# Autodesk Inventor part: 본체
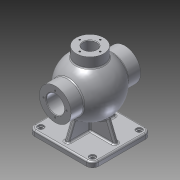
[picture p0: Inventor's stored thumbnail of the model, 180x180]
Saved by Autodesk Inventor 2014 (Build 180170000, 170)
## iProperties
Created: 2015-10
Part Number: 본체
Material: Aluminum 6061
Document SubType Name: Modeling
Designer: youjin20
Density: 2.71 g/cm^3
Appearance: Aluminum - Flat
Mass: 1509.58 g
Surface Area: 1153.86 cm^2
Volume: 557.04 cm^3
Author: youjin20
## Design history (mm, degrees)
sketch "Sketch2"
  geometry: L1 (50.5, -57.5)-(-50.5, -57.5); L2 (-62.5, -45.5)-(-62.5, 45.5); L3 (-50.5, 57.5)-(50.5, 57.5); L4 (62.5, 45.5)-(62.5, -45.5); L5 (62.5, -57.5)-(-62.5, 57.5); L6 (-62.5, -57.5)-(62.5, 57.5); A1 r 12 centre (50.5, 45.5) between (62.5, 45.5) and (50.5, 57.5); A2 r 12 centre (-50.5, 45.5) between (-50.5, 57.5) and (-62.5, 45.5); A3 r 12 centre (-50.5, -45.5) between (-62.5, -45.5) and (-50.5, -57.5); A4 r 12 centre (50.5, -45.5) between (50.5, -57.5) and (62.5, -45.5); 1 further point
  constraints: 12 end point, 8 point on circle, 8 point on line, 8 tangent, 4 centre point, 3 equal radius, 2 midpoint, 2 parallel, 1 horizontal, 1 perpendicular
  dimensions: "d0" = 125 distance of L5.end L6.end; "d1" = 115 distance of L6.start L5.end; "d2" = 12 radius of A1; "d3" = 101 distance of A2.centre A1.centre (derived)
extrude "Extrusion1" new body sketch "Sketch2" distance "d4" = 10; taper "d5" = 0 deg
sketch "Sketch3"
  geometry: A1 r 12 centre (50.5, -45.5) between (50.5, -57.5) and (62.5, -45.5) reference; A2 r 12 centre (50.5, 45.5) between (62.5, 45.5) and (50.5, 57.5) reference; A3 r 12 centre (-50.5, 45.5) between (-50.5, 57.5) and (-62.5, 45.5) reference; A4 r 12 centre (-50.5, -45.5) between (-62.5, -45.5) and (-50.5, -57.5) reference; 5 further points
  constraints: 4 coincident
hole "Hole1" sketch "Sketch3" at (-50.5, 45.5), (50.5, 45.5), (50.5, -45.5), (-50.5, -45.5) diameter "d6" = 8; stored, may be unused: countersink angle "d10" = 90 deg, drill point angle "d12" = 0 deg; dims "d7" = 6, "d8" = 12, "d9" = 3, "d11" = 8
sketch "Sketch4"
  geometry: L1 (-53, 85)-(-43, 85); L2 (-43, 85)-(43, 85); L3 (43, 85)-(53, 85); A1 r 53 centre (0, 85) between (-53, 85) and (53, 85); A2 r 43 centre (0, 85) between (-43, 85) and (43, 85); 2 further points
  constraints: 6 end point, 4 point on circle, 3 horizontal, 2 centre point, 2 coincident, 1 midpoint, 1 point on line, 1 vertical alignment
  dimensions: "d13" = 53 radius of A1; "d14" = 43 radius of A2; "d15" = 85 distance of point (0, 0) A2.centre
revolve "Revolution1" sketch "Sketch4" stored, may be unused: angle "d16" = 90 deg
workplane "Work Plane1"
sketch "Sketch5"
  geometry: C1 r 27 at (0, 0); 1 further point
  constraints: 1 centre point, 1 coincident
  dimensions: "d18" = 54 diameter of C1
extrude "Extrusion2" join sketch "Sketch5" stored distance "d19" = 10; taper "d20" = 0 deg
workplane "Work Plane2"
sketch "Sketch6"
  geometry: L1 (0, -27)-(0, 27) reference; L2 (0, 27)-(19.393, 27) reference; L3 (0, -27)-(19.393, -27) reference; 3 further points
  constraints: 1 horizontal alignment, 1 midpoint, 1 other
  dimensions: "d21" = 10 distance from line of point (10, 0) L1; "d120" = 27 distance from line of L3 point (10, 0) (derived)
emboss "Emboss1" sketch "Sketch6" dims "d0" = 125, "d1" = 115, "d2" = 12, "d3" = 101 (derived), "d23" = 0.5, "d24" = 0
sketch "Sketch7"
  geometry: L1 (4, 4)-(-4, 4); L2 (-4, 4)-(-4, -4); L3 (-4, -4)-(4, -4); L4 (4, -4)-(4, 4); L5 (4, 4)-(-4, -4); L6 (-4, 4)-(4, -4); 1 further point
  constraints: 12 end point, 2 midpoint, 2 parallel, 1 horizontal, 1 perpendicular
  dimensions: "d25" = 8 distance of L3.end L2.end; "d26" = 8 distance of L2.end L1.end
extrude "Extrusion3" join sketch "Sketch7" stored distance "d27" = 10; taper "d28" = 0 deg
sketch "Sketch8"
  geometry: L1 (-52.5, 10)-(-37.379, 47.426); L2 (52.5, 10)-(37.379, 47.426); L3 (62.5, 10)-(50.5, 10) reference; L4 (62.5, 0)-(62.5, 10) reference; L5 (-50.5, 10)-(-62.5, 10) reference; L6 (-62.5, 0)-(-62.5, 10) reference; A1 r 53 centre (0, 85) between (-27, 130.607) and (27, 130.607) reference; 1 further point
  constraints: 4 end point, 2 point on circle, 2 point on line
  dimensions: "d29" = 22 deg angle of L6 L1; "d30" = 22 deg angle of L2 L4; "d31" = 10 distance of L5.end L1.start; "d32" = 10 distance of L3.start L2.start
feature "Rib1" dims "d33" = 1, "d34" = 8, "d35" = 0, "d36" = 0, "d37" = 1, "d38" = 1
feature "Rib2" dims "d39" = 1, "d40" = 8, "d41" = 0, "d42" = 0, "d43" = 1, "d44" = 1
sketch "Sketch9"
  geometry: L1 (10, 47.5)-(44.109, 33.719); L2 (10, -47.5)-(44.109, -33.719); L3 (10, 45.5)-(10, 57.5) reference; L4 (0, 57.5)-(10, 57.5) reference; L5 (10, -57.5)-(10, -45.5) reference; L6 (0, -57.5)-(10, -57.5) reference; A1 r 53 centre (85, 0) between (130.607, 27) and (130.607, -27) reference; 1 further point
  constraints: 4 end point, 2 point on circle, 2 point on line
  dimensions: "d45" = 22 deg angle of L4 L1; "d46" = 22 deg angle of L2 L6; "d47" = 10 distance of L5.start L2.start; "d48" = 10 distance from line of L4 L1.start
feature "Rib3" dims "d49" = 1, "d50" = 8, "d51" = 0, "d52" = 0, "d53" = 1, "d54" = 1
feature "Rib4" dims "d55" = 1, "d56" = 8, "d57" = 0, "d58" = 0, "d59" = 1, "d60" = 1
workplane "Work Plane3"
sketch "Sketch10"
  geometry: L1 (-50.5, 0)-(50.5, 0) reference; C1 r 31 at (0, 85); 1 further point
  constraints: 1 centre point, 1 vertical alignment
  dimensions: "d62" = 62 diameter of C1; "d63" = 85 distance from line of L1 C1.centre
extrude "Extrusion4" join sketch "Sketch10" stored distance "d64" = 10; taper "d65" = 0 deg
fillet "Fillet1" dims "d66" = 3
sketch "Sketch11"
  geometry: C1 r 31 at (0, 0) reference; C2 r 17.5 at (0, 0); 1 further point
  constraints: 1 centre point, 1 coincident
  dimensions: "d67" = 35 diameter of C2
extrude "Extrusion5" cut sketch "Sketch11" stored distance "d68" = 10; taper "d69" = 0 deg
mirror "Mirror1"
sketch "Sketch12"
  geometry: L1 (54, -68)-(116, -68) reference; L2 (85, -38.465)-(85, -68); L3 (85, -38.465)-(102.5, -38.465); L4 (102.5, -38.465)-(102.5, -50.25); L5 (102.5, -50.25)-(103.5, -50.25); L6 (103.5, -50.25)-(103.5, -52); L7 (103.5, -52)-(102.5, -52); L8 (102.5, -52)-(102.5, -68); L9 (102.5, -68)-(85, -68); L10 (102.5, 39.278)-(67.5, 39.278) reference; 1 further point
  constraints: 16 end point, 5 perpendicular, 3 parallel, 2 midpoint, 1 collinear, 1 point on line
  dimensions: "d70" = 35 diameter of L8 L2; "d71" = 16 distance between parallel lines of L1 L7; "d72" = 37 diameter of L6 L2; "d73" = 1.75 distance from line of L7.end L5
revolve "Revolution2" sketch "Sketch12" stored, may be unused: angle "d74" = 90 deg
sketch "Sketch13" dims "d75" = 45
  geometry: C1 r 31 at (0, 0) reference; 6 further points
  constraints: 2 vertical alignment, 1 coincident, 7 other
  dimensions: "d78" = 360 deg dimension on point (0, 0) point (0, 22.5) (derived)
hole "Hole2" sketch "Sketch13" at (0, 22.5), (-22.5, 0), (0, -22.5), (22.5, 0) diameter "d80" = 3.242; stored, may be unused: countersink angle "d84" = 90 deg, drill point angle "d86" = 118 deg; dims "d81" = 12, "d82" = 12, "d83" = 3, "d85" = 15
sketch "Sketch14"
  geometry: C1 r 27 at (0, 0) reference; C2 r 13 at (0, 0)
  constraints: 1 centre point, 1 coincident
  dimensions: "d87" = 26 diameter of C2
extrude "Extrusion6" cut sketch "Sketch14" stored distance "d88" = 10; taper "d89" = 0 deg
sketch "Sketch15" dims "d90" = 40
  geometry: C1 r 27 at (0, 0) reference; 5 further points
  constraints: 2 vertical alignment, 1 coincident, 7 other
  dimensions: "d93" = 360 deg dimension on point (0, 0) point (0, 20) (derived)
hole "Hole3" sketch "Sketch15" at (0, 20), (-20, 0), (0, -20), (20, 0) diameter "d95" = 3.242; stored, may be unused: countersink angle "d99" = 90 deg, drill point angle "d101" = 118 deg; dims "d96" = 9, "d97" = 12, "d98" = 3, "d100" = 11
sketch "Sketch16" dims "d102" = 48
  geometry: C1 r 31 at (0, 0) reference; 6 further points
  constraints: 2 vertical alignment, 1 coincident, 7 other
  dimensions: "d105" = 360 deg dimension on point (0, 0) point (0, 24) (derived)
hole "Hole4" sketch "Sketch16" at (0, 24), (-24, 0), (0, -24), (24, 0) diameter "d107" = 3.242; stored, may be unused: countersink angle "d111" = 90 deg, drill point angle "d113" = 118 deg; dims "d108" = 16, "d109" = 12, "d110" = 3, "d112" = 19
fillet "Fillet2" dims "d114" = 3
fillet "Fillet3" dims "d115" = 3
fillet "Fillet4" dims "d116" = 3
chamfer "Chamfer1" distance "d117" = 1; stored, may be unused: second distance "d118" = 2, angle "d119" = 45 deg
body "Solid1"
node "Projected Loop1"
other parameters: "d61" = 68
